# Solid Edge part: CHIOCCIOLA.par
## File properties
Subject: CHIOCCIOLA
Author: Francesco
Template: Normal.par
Last saved by: f_grande
Revision: 7
Application: Solid Edge
Material: Acciaio
Stile della faccia: Acciaio
Stile di riempimento: ANSI32(Acciaio)
Stile virtuale: Acciaio lavorato a macchina
Coef. of Thermal Exp: 0.0
Thermal Conductivity: 32.0
Specific Heat: 481.0
Modulus of Elasticity: 199947953000.0
Poisson's Ratio: 0.29
Yield Stress: 262000766.0
Ultimate Stress: 358527364.0
Elongation: 0.0
Tipo di contenuto documento: 0
Densità: 7833,000 kg/m^3
Precisione: 0,990
Document Number: KR0134
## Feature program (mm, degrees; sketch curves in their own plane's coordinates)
sketch for "unnamed Protrusion 1" plane through (0, 0, 0) normal (0, -1, 0) x-axis (1, 0, 0)
  circle centre (0, 0) radius 24
extrude "unnamed Protrusion 1" add finite 42 along +normal
sketch for "ExtrudedCutout_2" #1 plane through (0, -42, 0) normal (0, -1, 0) x-axis (1, 0, 0)
  circle centre (0, 0) radius 13.65
sketch for "ExtrudedCutout_2" #2 plane through (0, -42, 0) normal (0, -1, 0) x-axis (1, 0, 0)
  circle centre (0, 0) radius 24.4382
extrude "ExtrudedCutout_2" cut finite 32 along -normal
sketch for "Foro_6" plane through (0, -42, 0) normal (0, -1, 0) x-axis (1, 0, 0)
  hole centre (0, 0) bore radius 8
hole "Foro_6" diameter 16 through
sketch for "ExtrudedCutout_3" #1 plane through (0, 0, 0) normal (0, 1, 0) x-axis (-1, 0, 0)
  line (28.0452, 20) -> (28.0452, 25.8178)
  line (28.0452, 25.8178) -> (-31.9548, 25.8178)
  line (-31.9548, 25.8178) -> (-31.9548, 20)
  line (-31.9548, 20) -> (28.0452, 20)
sketch for "ExtrudedCutout_3" #2 plane through (0, 0, 0) normal (0, 1, 0) x-axis (-1, 0, 0)
  line (28.0452, -20) -> (28.0452, -25.3796)
  line (28.0452, -25.3796) -> (-31.9548, -25.3796)
  line (-31.9548, -25.3796) -> (-31.9548, -20)
  line (-31.9548, -20) -> (28.0452, -20)
extrude "ExtrudedCutout_3" cut finite 232.1328 along -normal
sketch for "Foro_7" plane through (0, 0, 0) normal (0, 1, 0) x-axis (-1, 0, 0)
  hole centre (19, 0) bore radius 2.9
hole "Foro_7" diameter 5.8 through
sketch for "unnamed Hole 1" plane through (0, 0, 0) normal (0, 1, 0) x-axis (-1, 0, 0)
  hole centre (-13.45, 13.45) bore radius 2.9
hole "unnamed Hole 1" through
sketch for "unnamed Hole 2" plane through (0, 0, 0) normal (0, 1, 0) x-axis (-1, 0, 0)
  hole centre (13.45, 13.45) bore radius 2.9
hole "unnamed Hole 2" through
sketch for "unnamed Hole 3" plane through (0, 0, 0) normal (0, 1, 0) x-axis (-1, 0, 0)
  hole centre (-13.45, -13.45) bore radius 2.9
hole "unnamed Hole 3" through
sketch for "unnamed Hole 4" plane through (0, 0, 0) normal (0, 1, 0) x-axis (-1, 0, 0)
  hole centre (13.45, -13.45) bore radius 2.9
hole "unnamed Hole 4" through
sketch for "unnamed Hole 5" plane through (0, 0, 0) normal (0, 1, 0) x-axis (-1, 0, 0)
  hole centre (-19, 0) bore radius 2.9
hole "unnamed Hole 5" through
pattern "unnamed Pattern 1" of "Foro_7", "unnamed Hole 1", "unnamed Hole 2", "unnamed Hole 3", "unnamed Hole 4", "unnamed Hole 5"
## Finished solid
Body 1: solid body, 15 faces, 28 edges, 8 vertices.
  Faces by surface: cylinder 10, plane 5
  Edges by curve: circle 20, line 8
Bounding box of the edges (mm): 48.000 x 42.000 x 40.000, from (-24, -42, -20) to (24, 0, 20).
Cylindrical faces by radius (mm): R2.9 x6, R8 x1, R13.65 x1, R24 x2
Planar faces by outward normal: +y 1, +z 1, -y 2, -z 1
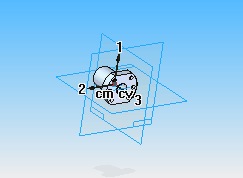
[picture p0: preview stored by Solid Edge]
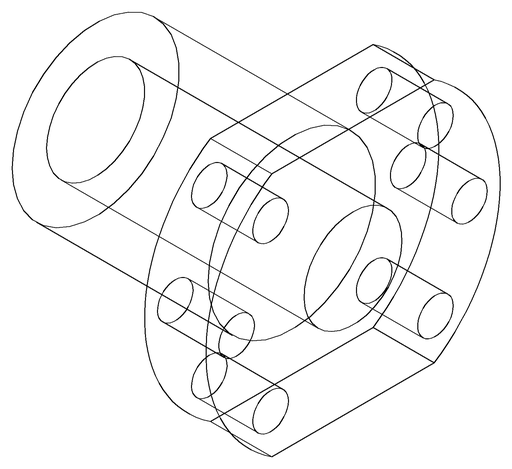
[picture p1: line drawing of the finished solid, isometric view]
